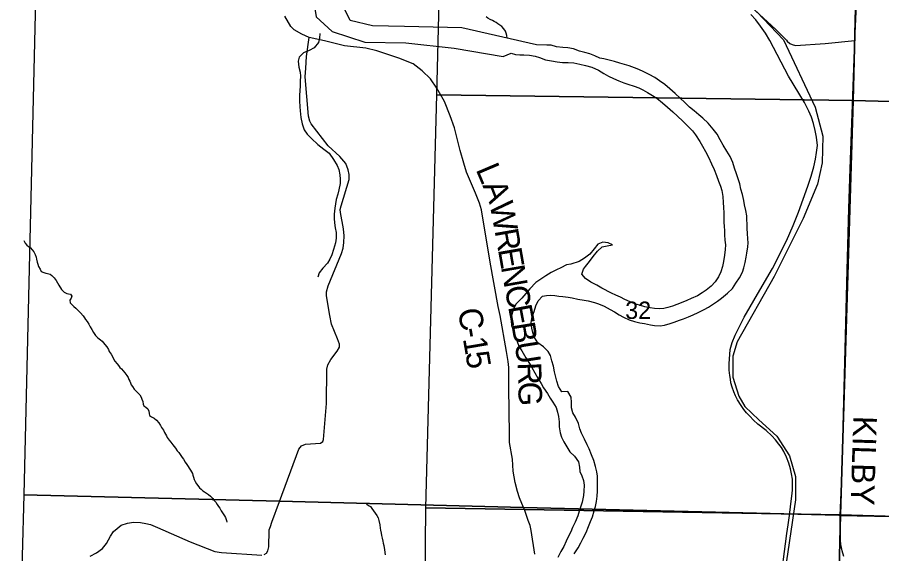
# Model space of a CAD drawing. Extents: x -7.5 to 26.5, y 3.5 to 25.5.
# Drawn here: x -5.3 to -3.216, y 19.097 to 20.391 of the extents above; entities that cross this region are included whole.
import ezdxf

# ---------------------------------------------------------------- set-up
doc = ezdxf.new("R2010")
doc.units = 0
for name, color, linetype in [('GM_X_Corporation', 7, 'Continuous'), ('GM_X_County_Road', 7, 'Continuous'), ('GM_X_County_Road_Text', 7, 'Continuous'), ('GM_X_Minor_River', 7, 'Continuous'), ('GM_X_Rail_Line', 7, 'Continuous'), ('GM_X_Section_Text', 7, 'Continuous')]:
    doc.layers.add(name, color=color, linetype=linetype)

msp = doc.modelspace()

# ---------------------------------------------------------------- linework, layer by layer
at = {"layer": 'GM_X_Corporation'}
for points in [[(-5.2204, 21.7606), (-5.2223, 21.6911), (-5.2307, 21.5062), (-5.2312, 21.4872), (-5.2369, 21.235), (-5.244, 21.0357), (-5.2442, 21.0272), (-5.2438, 21.0206), (-5.2429, 21.0142), (-5.2848, 19.2392), (-5.3003, 18.6476)], [(-5.2204, 21.7606), (-5.2223, 21.6911), (-5.2307, 21.5062), (-5.2312, 21.4872), (-5.2369, 21.235), (-5.244, 21.0357), (-5.2442, 21.0272), (-5.2438, 21.0206), (-5.2429, 21.0142), (-5.2848, 19.2392), (-4.6686, 19.2237), (-4.08, 19.2088), (-3.3198, 19.1896), (-3.3166, 19.1895), (-2.696, 19.1768)], [(-2.696, 19.1768), (-3.3166, 19.1895), (-3.3198, 19.1896), (-4.08, 19.2088), (-4.6686, 19.2237), (-5.2848, 19.2392), (-5.3003, 18.6476)]]:
    msp.add_lwpolyline(points, dxfattribs=at)
for points in [[(-4.2641, 21.1987), (-3.2602, 21.1789), (-3.2852, 20.1896), (-4.2892, 20.2036)], [(-3.2602, 21.1789), (-2.268, 21.1618), (-2.2948, 20.1631), (-3.2852, 20.1896)], [(-4.2892, 20.2036), (-3.2852, 20.1896), (-3.3161, 19.1909), (-4.3152, 19.2075)], [(-3.2852, 20.1896), (-2.2948, 20.1631), (-2.3216, 19.1609), (-3.3161, 19.1909)], [(-4.3152, 19.2075), (-3.3161, 19.1909), (-3.3388, 18.2326), (-4.3246, 18.2499)], [(-2.3216, 19.1609), (-2.3477, 18.203), (-3.3388, 18.2326), (-3.3161, 19.1909)]]:
    msp.add_lwpolyline(points, close=True, dxfattribs=at)
at = {"layer": 'GM_X_County_Road'}
for points in [[(-3.2809, 20.3346), (-3.2767, 20.4388), (-3.2721, 20.5738), (-3.2679, 20.7309), (-3.2662, 20.8902), (-3.2627, 20.9014), (-3.2568, 20.9105), (-3.2392, 20.9329), (-3.2245, 20.9523), (-3.2224, 20.9608), (-3.2224, 20.9618)], [(-3.5482, 20.4323), (-3.5206, 20.4061), (-3.4824, 20.3706), (-3.4713, 20.3604), (-3.4463, 20.3354), (-3.4442, 20.3333), (-3.4379, 20.3278), (-3.4327, 20.3249), (-3.4241, 20.3224), (-3.353, 20.3275), (-3.2809, 20.3346)], [(-4.053, 19.0957), (-4.0615, 19.153), (-4.0641, 19.1648), (-4.069, 19.1771), (-4.0776, 19.2032), (-4.0797, 19.2083), (-4.0899, 19.2317), (-4.0947, 19.2467), (-4.1, 19.2689), (-4.1051, 19.296), (-4.1064, 19.3249), (-4.1134, 19.365), (-4.1135, 19.3847), (-4.1153, 19.4975), (-4.1151, 19.5457), (-4.1169, 19.5609), (-4.121, 19.5846), (-4.1359, 19.6716), (-4.1408, 19.6934), (-4.1603, 19.8003), (-4.1814, 19.9263), (-4.1858, 19.9423), (-4.1956, 19.9666), (-4.2177, 20.0174), (-4.2242, 20.0385), (-4.2326, 20.0695), (-4.2467, 20.1239), (-4.2571, 20.1531), (-4.2703, 20.1877), (-4.2893, 20.2198), (-4.3045, 20.242), (-4.3239, 20.2612), (-4.3457, 20.2786), (-4.3805, 20.292), (-4.4334, 20.3097), (-4.4597, 20.3162), (-4.5115, 20.3222), (-4.56, 20.3337), (-4.5965, 20.3421), (-4.6141, 20.3503), (-4.6327, 20.3604), (-4.6407, 20.3686), (-4.6554, 20.393)], [(-4.5639, 19.3672), (-4.5618, 19.3724), (-4.555, 19.4595), (-4.5545, 19.5422), (-4.5515, 19.5527), (-4.5442, 19.565), (-4.5291, 19.5858), (-4.5235, 19.5947), (-4.5236, 19.6023), (-4.5281, 19.615), (-4.5428, 19.6507), (-4.547, 19.6714), (-4.5553, 19.7187), (-4.5549, 19.7282), (-4.551, 19.7429), (-4.5188, 19.8211), (-4.5149, 19.8335), (-4.5133, 19.8475), (-4.512, 19.8634), (-4.5137, 19.8805), (-4.5214, 19.9198), (-4.5216, 19.9271), (-4.5198, 19.9361), (-4.5005, 19.9996), (-4.5005, 20.0117), (-4.5028, 20.0228), (-4.5087, 20.0382), (-4.5229, 20.055), (-4.5512, 20.081), (-4.5922, 20.134), (-4.5954, 20.1405), (-4.5981, 20.1524), (-4.6062, 20.2468), (-4.6051, 20.268), (-4.6034, 20.296), (-4.5965, 20.3421)], [(-3.3163, 19.189), (-3.313, 19.2815), (-3.3077, 19.4645), (-3.3047, 19.5899), (-3.3, 19.7809), (-3.2955, 19.9295), (-3.2923, 20.0251), (-3.2809, 20.3346)], [(-4.693, 19.1544), (-4.6903, 19.1624), (-4.6869, 19.1732), (-4.6684, 19.2232), (-4.6214, 19.3494), (-4.6154, 19.3568), (-4.6058, 19.3614), (-4.5693, 19.3636), (-4.5639, 19.3672)], [(-5.1244, 19.0908), (-5.1097, 19.099), (-5.0953, 19.1099), (-5.0854, 19.1217), (-5.0757, 19.1392), (-5.0681, 19.1504), (-5.0599, 19.1581), (-5.0498, 19.1657), (-5.0348, 19.1705), (-5.0199, 19.1734), (-5.0033, 19.1721), (-4.9901, 19.1701), (-4.9792, 19.1675), (-4.9623, 19.1605), (-4.8839, 19.126), (-4.8244, 19.1023), (-4.8082, 19.0995), (-4.7109, 19.0936)], [(-3.3081, 19.0903), (-3.312, 19.1039), (-3.3137, 19.1117), (-3.315, 19.119), (-3.3161, 19.1296), (-3.3162, 19.1422), (-3.316, 19.1574), (-3.3163, 19.189)], [(-4.7048, 19.0953), (-4.6997, 19.0982), (-4.6965, 19.1037), (-4.6943, 19.1135), (-4.6933, 19.1533), (-4.693, 19.1544)]]:
    msp.add_lwpolyline(points, dxfattribs=at)
at = {"layer": 'GM_X_Minor_River'}
for points in [[(-4.6091, 20.5014), (-4.5903, 20.4564), (-4.5796, 20.3917), (-4.5414, 20.3565), (-4.4626, 20.3304), (-4.3638, 20.3293), (-4.2472, 20.3158), (-4.1289, 20.296)], [(-4.0483, 20.3243), (-4.2286, 20.3653), (-4.3667, 20.3688), (-4.4439, 20.3703), (-4.4977, 20.3831), (-4.5285, 20.4455)], [(-4.1191, 20.3404), (-4.1202, 20.3465), (-4.1215, 20.3527), (-4.1233, 20.3569), (-4.1276, 20.3628), (-4.132, 20.3682), (-4.1368, 20.3718), (-4.1416, 20.3746), (-4.1461, 20.3778), (-4.1506, 20.3803), (-4.155, 20.3831), (-4.1606, 20.3852), (-4.1662, 20.3884), (-4.1703, 20.3916)], [(-4.5708, 20.3516), (-4.5715, 20.3399), (-4.574, 20.3301), (-4.5846, 20.3167), (-4.5969, 20.3102), (-4.6103, 20.3052), (-4.6212, 20.2945), (-4.623, 20.2846), (-4.6218, 20.2706), (-4.6183, 20.2583), (-4.6178, 20.2485), (-4.6181, 20.2363), (-4.6188, 20.2265), (-4.6191, 20.2128), (-4.6197, 20.2033), (-4.6197, 20.1889), (-4.619, 20.1745), (-4.6185, 20.165), (-4.6166, 20.149), (-4.6136, 20.1337), (-4.609, 20.1196), (-4.6017, 20.1091), (-4.5914, 20.0986), (-4.5762, 20.0842), (-4.5617, 20.0728), (-4.5487, 20.0626), (-4.5377, 20.0479), (-4.5294, 20.0333), (-4.5255, 20.0233), (-4.5224, 20.0107), (-4.5219, 20.0005), (-4.5222, 19.9899), (-4.5248, 19.9744), (-4.5278, 19.9642), (-4.5315, 19.951), (-4.5333, 19.9408), (-4.5351, 19.9302), (-4.5366, 19.9155), (-4.5368, 19.9056), (-4.536, 19.8953), (-4.534, 19.8831), (-4.532, 19.8713), (-4.5313, 19.8576), (-4.5331, 19.8471), (-4.538, 19.8309), (-4.5418, 19.8181), (-4.547, 19.8072), (-4.5529, 19.7975), (-4.5638, 19.786), (-4.5724, 19.7741), (-4.5761, 19.7643)], [(-4.0234, 20.3236), (-4.0483, 20.3243)], [(-4.0234, 20.3236), (-4.0483, 20.3243)], [(-3.9851, 19.7169), (-3.9726, 19.7159), (-3.9628, 19.7137), (-3.9488, 19.7107), (-3.9341, 19.7088), (-3.9239, 19.707), (-3.9092, 19.7032), (-3.8991, 19.6999), (-3.8856, 19.6939), (-3.871, 19.6859), (-3.861, 19.68), (-3.8494, 19.6729), (-3.8386, 19.6673), (-3.8254, 19.6612), (-3.8123, 19.6571), (-3.7999, 19.6541), (-3.7882, 19.6519), (-3.7742, 19.6489), (-3.7644, 19.6471), (-3.7508, 19.6464), (-3.7401, 19.6484), (-3.7268, 19.6519), (-3.7172, 19.655), (-3.7038, 19.66), (-3.6943, 19.6632), (-3.682, 19.6686), (-3.6713, 19.6732), (-3.6587, 19.6786), (-3.6444, 19.6858), (-3.6341, 19.6912), (-3.6217, 19.6993), (-3.6121, 19.7059), (-3.6024, 19.7132), (-3.5885, 19.725), (-3.5764, 19.7364), (-3.5678, 19.7491), (-3.5591, 19.7622), (-3.5523, 19.7757), (-3.549, 19.7862), (-3.5456, 19.7994), (-3.5431, 19.8119), (-3.5417, 19.8221), (-3.5394, 19.8368), (-3.5387, 19.8467), (-3.5389, 19.8562), (-3.5401, 19.8691), (-3.5409, 19.8813), (-3.541, 19.8923), (-3.5415, 19.9018), (-3.542, 19.912), (-3.5439, 19.925), (-3.547, 19.9383), (-3.549, 19.9486), (-3.552, 19.9635), (-3.5559, 19.9761), (-3.5589, 19.9891), (-3.5635, 20.0033), (-3.5667, 20.0132), (-3.5716, 20.0266), (-3.5754, 20.0408), (-3.5819, 20.0546), (-3.5895, 20.0677), (-3.5986, 20.082), (-3.6062, 20.0955), (-3.6135, 20.1086), (-3.6226, 20.1209), (-3.6351, 20.1357), (-3.6473, 20.1474), (-3.657, 20.1552), (-3.6685, 20.165), (-3.6796, 20.1736), (-3.6911, 20.1849), (-3.7025, 20.1958), (-3.7144, 20.2072), (-3.7273, 20.2181), (-3.7392, 20.2287), (-3.7519, 20.237), (-3.7638, 20.2456), (-3.7772, 20.2524), (-3.7896, 20.2592), (-3.8023, 20.2644), (-3.8121, 20.2689), (-3.8252, 20.2738), (-3.8369, 20.2771), (-3.8478, 20.2804), (-3.8605, 20.2841), (-3.8737, 20.2875), (-3.8865, 20.2901), (-3.8963, 20.2919), (-3.9083, 20.2975), (-3.9203, 20.3024), (-3.9324, 20.3057), (-3.9452, 20.3091), (-3.9594, 20.3144), (-3.973, 20.317), (-3.9855, 20.3181), (-4.0006, 20.3196), (-4.013, 20.3233), (-4.0234, 20.3236)], [(-4.1289, 20.296), (-4.1098, 20.3038), (-4.0992, 20.3013), (-4.089, 20.2999), (-4.0795, 20.3004), (-4.0659, 20.2993), (-4.0516, 20.297), (-4.0411, 20.2933), (-4.0268, 20.2884), (-4.0128, 20.2858), (-3.9992, 20.2835), (-3.986, 20.282), (-3.972, 20.2817), (-3.9584, 20.2806), (-3.9445, 20.2776), (-3.9305, 20.2742), (-3.9151, 20.27), (-3.8994, 20.2631), (-3.8863, 20.2548), (-3.8755, 20.2485), (-3.8631, 20.2428), (-3.8504, 20.2376), (-3.838, 20.2327), (-3.8282, 20.229), (-3.8132, 20.2245), (-3.8019, 20.2204), (-3.7922, 20.2156), (-3.7814, 20.2093), (-3.7687, 20.2021), (-3.7586, 20.1954), (-3.7449, 20.1844), (-3.733, 20.1735), (-3.7201, 20.1625), (-3.709, 20.1524), (-3.6956, 20.1399), (-3.6827, 20.127), (-3.6728, 20.1165), (-3.6654, 20.1069), (-3.6548, 20.0914), (-3.6487, 20.0799), (-3.6411, 20.0668), (-3.6338, 20.0537), (-3.627, 20.0376), (-3.6206, 20.0233), (-3.6145, 20.0088), (-3.6096, 19.9957), (-3.6053, 19.9831), (-3.6022, 19.9728), (-3.5995, 19.9587), (-3.5984, 19.9438), (-3.5976, 19.9321), (-3.5971, 19.9188), (-3.597, 19.9078), (-3.597, 19.8964), (-3.5961, 19.8861), (-3.5956, 19.8762), (-3.5955, 19.8656), (-3.5947, 19.8534), (-3.5934, 19.842), (-3.5937, 19.831), (-3.5952, 19.817), (-3.5975, 19.8015), (-3.6005, 19.7898), (-3.6042, 19.777), (-3.6098, 19.7646), (-3.6181, 19.7527), (-3.6278, 19.7419), (-3.6395, 19.7324), (-3.6495, 19.7262), (-3.6606, 19.7189), (-3.676, 19.7124), (-3.6863, 19.7078), (-3.7001, 19.7017), (-3.7104, 19.6981), (-3.7211, 19.6942), (-3.7322, 19.6911), (-3.7421, 19.6887), (-3.7531, 19.6878), (-3.7641, 19.6885), (-3.7743, 19.6899), (-3.7875, 19.6921), (-3.8007, 19.6963), (-3.8116, 19.6992), (-3.8232, 19.7041), (-3.8359, 19.7101), (-3.846, 19.7153), (-3.8576, 19.7205), (-3.8681, 19.7253), (-3.8913, 19.7377), (-3.9036, 19.7448), (-3.9175, 19.752), (-3.9309, 19.7603), (-3.9393, 19.7712), (-3.9352, 19.7832)], [(-5.2846, 19.8521), (-5.281, 19.8462), (-5.2777, 19.8408), (-5.2733, 19.8376), (-5.2688, 19.8348), (-5.2641, 19.8297), (-5.2604, 19.8246), (-5.2569, 19.8188), (-5.2548, 19.8123), (-5.2542, 19.8077), (-5.2522, 19.7997), (-5.2508, 19.795), (-5.2491, 19.79), (-5.2455, 19.7835), (-5.2427, 19.7777), (-5.2364, 19.7748), (-5.2315, 19.7735), (-5.2273, 19.773), (-5.2213, 19.7712), (-5.2168, 19.768), (-5.2113, 19.7625), (-5.207, 19.7559), (-5.2034, 19.7501), (-5.2002, 19.7443), (-5.1937, 19.7338), (-5.1871, 19.7275), (-5.1811, 19.7246), (-5.1766, 19.7241), (-5.1721, 19.7228), (-5.1692, 19.7177), (-5.1705, 19.7136), (-5.1737, 19.7088), (-5.1728, 19.7023), (-5.1691, 19.698), (-5.1644, 19.6933), (-5.1596, 19.6889), (-5.1533, 19.6838), (-5.1478, 19.6779), (-5.1416, 19.6704), (-5.1384, 19.6661), (-5.1355, 19.6619), (-5.1318, 19.6568), (-5.1279, 19.6502), (-5.1247, 19.644), (-5.1207, 19.6374), (-5.1164, 19.6304), (-5.1117, 19.6234), (-5.1058, 19.6179), (-5.0996, 19.6127), (-5.0955, 19.6092), (-5.0889, 19.6017), (-5.0842, 19.5959), (-5.0806, 19.5897), (-5.0785, 19.585), (-5.0742, 19.5784), (-5.071, 19.5726), (-5.0681, 19.5668), (-5.0649, 19.5614), (-5.0598, 19.5551), (-5.0561, 19.5508), (-5.0529, 19.5462), (-5.0488, 19.5426), (-5.0452, 19.5383), (-5.0412, 19.5328), (-5.0365, 19.527), (-5.0332, 19.5219), (-5.0311, 19.5173), (-5.029, 19.513), (-5.0272, 19.5088), (-5.0259, 19.5046), (-5.0226, 19.4999), (-5.0186, 19.4937), (-5.0139, 19.4886), (-5.0095, 19.4846), (-5.0051, 19.4799), (-5.0018, 19.4748), (-4.9997, 19.4698), (-4.998, 19.4637), (-4.9967, 19.4579), (-4.995, 19.4537), (-4.9901, 19.4501), (-4.9857, 19.4462), (-4.9833, 19.4408), (-4.9827, 19.435), (-4.9817, 19.4305), (-4.9769, 19.4269), (-4.9706, 19.4236), (-4.965, 19.4189), (-4.9595, 19.413), (-4.9548, 19.406), (-4.9527, 19.401), (-4.9476, 19.3947), (-4.9456, 19.3889), (-4.9405, 19.3815), (-4.9387, 19.3773), (-4.934, 19.371), (-4.93, 19.366), (-4.9253, 19.3597), (-4.9191, 19.3515), (-4.9148, 19.3453), (-4.9108, 19.341)], [(-3.9352, 19.7832), (-3.9305, 19.7899), (-3.9207, 19.8018), (-3.9121, 19.8134), (-3.9019, 19.8268), (-3.8903, 19.8367), (-3.8785, 19.8394), (-3.8651, 19.8421), (-3.876, 19.8466), (-3.8888, 19.8481), (-3.9011, 19.8438), (-3.9097, 19.8319), (-3.9203, 19.8193), (-3.933, 19.8097), (-3.9457, 19.8013), (-3.966, 19.7954)], [(-3.966, 19.7954), (-3.9766, 19.7934), (-3.9901, 19.7865), (-4.0004, 19.7818), (-4.0131, 19.775), (-4.0262, 19.7673), (-4.0501, 19.7512), (-4.0645, 19.7357), (-4.084, 19.7134), (-4.0977, 19.6997), (-4.1048, 19.6862), (-4.1086, 19.6708), (-4.1097, 19.6594), (-4.1089, 19.6472), (-4.1046, 19.6365), (-4.1, 19.6227), (-4.0955, 19.6086), (-4.0912, 19.5978), (-4.0843, 19.5859), (-4.0745, 19.5697), (-4.0658, 19.5554), (-4.0599, 19.5458), (-4.0527, 19.5335), (-4.0455, 19.52), (-4.0378, 19.5073), (-4.0317, 19.4969), (-4.0225, 19.4837), (-4.0156, 19.4722), (-4.009, 19.4625), (-4.001, 19.4494), (-3.9979, 19.4387), (-3.9955, 19.428), (-3.9944, 19.4147), (-3.9939, 19.4026), (-3.9916, 19.3884), (-3.9885, 19.3781), (-3.9827, 19.3666), (-3.9758, 19.3547), (-3.9686, 19.3423), (-3.9567, 19.3325), (-3.9472, 19.3182), (-3.9453, 19.3053), (-3.944, 19.2954), (-3.9397, 19.285), (-3.9351, 19.2732), (-3.9339, 19.2621), (-3.9346, 19.2481), (-3.9353, 19.2375), (-3.9387, 19.2216), (-3.9428, 19.2096), (-3.9461, 19.1994), (-3.9494, 19.1881), (-3.9555, 19.1727), (-3.9615, 19.1604), (-3.9663, 19.1495), (-3.9723, 19.1375), (-3.9775, 19.127), (-3.9828, 19.1146), (-3.9903, 19.1023), (-3.9971, 19.0877)], [(-3.9578, 19.0965), (-3.948, 19.1111), (-3.942, 19.1234), (-3.936, 19.1347), (-3.9288, 19.1485), (-3.9232, 19.1628), (-3.9183, 19.1748), (-3.9139, 19.1857), (-3.9097, 19.2004), (-3.9064, 19.2109), (-3.9042, 19.223), (-3.9027, 19.2355), (-3.902, 19.2476), (-3.9013, 19.2601), (-3.9014, 19.2723), (-3.9015, 19.2837), (-3.9031, 19.2943), (-3.9062, 19.3073), (-3.9104, 19.3219), (-3.9157, 19.3357), (-3.9214, 19.3498), (-3.9264, 19.3598), (-3.9329, 19.3729), (-3.9401, 19.3879), (-3.9444, 19.3979), (-3.9475, 19.4108), (-3.955, 19.4262), (-3.9608, 19.437), (-3.9647, 19.4489), (-3.9647, 19.4618), (-3.9655, 19.4747), (-3.9731, 19.4885), (-3.9879, 19.4874), (-3.9956, 19.5001), (-3.9998, 19.5128), (-4.0029, 19.5257), (-4.0053, 19.5357), (-4.008, 19.549), (-4.0114, 19.562), (-4.0153, 19.5746), (-4.0207, 19.5846), (-4.0318, 19.5959), (-4.0451, 19.6054), (-4.0535, 19.6185), (-4.0574, 19.6304), (-4.0598, 19.641), (-4.0617, 19.6548), (-4.0591, 19.668), (-4.0542, 19.6815), (-4.0504, 19.6951), (-4.0444, 19.7071), (-4.0339, 19.7178), (-4.0244, 19.7195), (-4.0149, 19.7207), (-4.0047, 19.7197), (-3.9949, 19.7179), (-3.9851, 19.7169)], [(-4.9108, 19.341), (-4.9079, 19.3363), (-4.9025, 19.3289), (-4.8996, 19.3246), (-4.8956, 19.3177), (-4.8913, 19.3118), (-4.8884, 19.3075), (-4.8859, 19.3029), (-4.8826, 19.2982), (-4.8783, 19.2905), (-4.8773, 19.2862), (-4.8752, 19.2816), (-4.8743, 19.2763), (-4.8718, 19.2709), (-4.8686, 19.2654), (-4.8649, 19.2611), (-4.8613, 19.2557), (-4.8569, 19.2529), (-4.8528, 19.2489), (-4.8487, 19.2465), (-4.8443, 19.2429), (-4.8391, 19.2401), (-4.8343, 19.2357), (-4.8292, 19.2302), (-4.8259, 19.2256), (-4.8215, 19.2209), (-4.8186, 19.2158), (-4.8154, 19.2111), (-4.8118, 19.2065), (-4.8085, 19.2006), (-4.8042, 19.1933), (-4.801, 19.1882), (-4.7985, 19.184), (-4.7961, 19.1774), (-4.7954, 19.1732)], [(-4.4587, 19.2171), (-4.4535, 19.2135), (-4.449, 19.2107), (-4.4454, 19.2056), (-4.4414, 19.2005), (-4.4374, 19.1951), (-4.4338, 19.1892), (-4.4306, 19.1838), (-4.4289, 19.1773), (-4.4266, 19.1666), (-4.4254, 19.1585), (-4.4248, 19.154), (-4.4231, 19.1467), (-4.4222, 19.1406), (-4.4209, 19.1344), (-4.4192, 19.1275), (-4.4187, 19.1226), (-4.417, 19.1165), (-4.4154, 19.1065), (-4.4136, 19.0939)]]:
    msp.add_lwpolyline(points, dxfattribs=at)
at = {"layer": 'GM_X_Rail_Line'}
for points in [[(-3.5178, 20.4035), (-3.4532, 20.3366), (-3.3767, 20.1739), (-3.3584, 20.1039), (-3.3602, 20.0395), (-3.3716, 19.9879), (-3.4059, 19.9057), (-3.4761, 19.7658), (-3.5651, 19.6083), (-3.5755, 19.5734), (-3.5755, 19.5231), (-3.5608, 19.4768), (-3.5466, 19.4517), (-3.5126, 19.42), (-3.4694, 19.3801), (-3.4387, 19.3333), (-3.4245, 19.2829), (-3.4242, 19.2265), (-3.4542, 19.0248)], [(-3.4591, 19.0404), (-3.4481, 19.1211), (-3.4448, 19.1458), (-3.442, 19.1663), (-3.4389, 19.1895), (-3.4352, 19.217), (-3.4329, 19.2358), (-3.4313, 19.2506), (-3.4314, 19.2646), (-3.4319, 19.2771), (-3.4337, 19.2893), (-3.4362, 19.3017), (-3.4403, 19.3155), (-3.4457, 19.3299), (-3.4523, 19.3431), (-3.4584, 19.3532), (-3.4641, 19.3612), (-3.4724, 19.3719), (-3.481, 19.3812), (-3.4949, 19.3938), (-3.5149, 19.4097), (-3.5254, 19.4193), (-3.5347, 19.4285), (-3.5424, 19.4369), (-3.5488, 19.445), (-3.5549, 19.4543), (-3.564, 19.4681), (-3.5693, 19.4774), (-3.5732, 19.4873), (-3.5769, 19.4985), (-3.5799, 19.5092), (-3.5814, 19.518), (-3.5827, 19.5265), (-3.5839, 19.5393), (-3.5845, 19.555), (-3.5821, 19.5897), (-3.5769, 19.6062), (-3.5699, 19.6241), (-3.5484, 19.6673), (-3.51, 19.7327), (-3.4797, 19.7847), (-3.4464, 19.8514), (-3.4303, 19.8886), (-3.4173, 19.921), (-3.3946, 19.983), (-3.3865, 20.0078), (-3.3799, 20.03), (-3.3761, 20.0486), (-3.3734, 20.0646), (-3.3716, 20.0815), (-3.3739, 20.1016), (-3.3765, 20.1173), (-3.3808, 20.1346), (-3.3859, 20.1498), (-3.3925, 20.1645), (-3.4026, 20.1848), (-3.4412, 20.2486), (-3.486, 20.3345), (-3.4967, 20.3524), (-3.5084, 20.3695), (-3.5203, 20.3848), (-3.5317, 20.3974)]]:
    msp.add_lwpolyline(points, dxfattribs=at)

# ---------------------------------------------------------------- texts
at = {"layer": 'GM_X_County_Road_Text'}
for s, height, rotation, p in [('L', 0.0568, 293.0029, (-4.1958, 20.0238)), ('A', 0.0568, 291.2563, (-4.1794, 19.9851)), ('W', 0.0568, 280.6537, (-4.162, 19.9411)), ('R', 0.0568, 279.9203, (-4.1499, 19.8766)), ('E', 0.0568, 279.92, (-4.1418, 19.8307)), ('N', 0.0568, 279.9249, (-4.1345, 19.7888)), ('C', 0.0568, 280.3112, (-4.1258, 19.7391)), ('E', 0.0568, 280.7765, (-4.1174, 19.6927)), ('C', 0.0568, 280.7002, (-4.2389, 19.6844)), ('B', 0.0568, 279.4114, (-4.1095, 19.6513)), ('-', 0.0568, 279.8744, (-4.2303, 19.6388)), ('1', 0.0568, 279.6289, (-4.2263, 19.6158)), ('U', 0.0568, 278.9134, (-4.1019, 19.6054)), ('5', 0.0568, 279.5563, (-4.2204, 19.5813)), ('R', 0.0568, 272.1339, (-4.0943, 19.5578)), ('G', 0.0568, 270.8946, (-4.0926, 19.5115)), ('KILBY', 0.05682, 268.2031, (-3.2847, 19.43))]:
    msp.add_text(s, height=height, rotation=rotation, dxfattribs=at).set_placement(p)
at = {"layer": 'GM_X_Section_Text'}
msp.add_text('32', height=0.04186, rotation=0, dxfattribs=at).set_placement((-3.8347, 19.6632))

doc.saveas('drawing.dxf')
